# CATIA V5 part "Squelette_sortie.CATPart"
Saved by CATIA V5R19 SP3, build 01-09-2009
Part number: Squelette_sortie
Bounding box of the stored display mesh (mm): x 0 to 0, y 0 to 43, z -18 to 18
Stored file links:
  C:\Users\Frédéric\Documents\WF\STSCPI 09-11\Projets\Projet multiplicateur eolienne\Maquette eolienne\Squelette_sortie.CATPart
  C:\Users\Frédéric\Documents\WF\STSCPI 09-11\Projets\Projet multiplicateur eolienne\Maquette eolienne\Multiplicateur_eolien.CATProduct
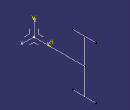
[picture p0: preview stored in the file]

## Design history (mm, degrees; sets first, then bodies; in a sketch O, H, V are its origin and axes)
External parameters (linked from other documents)
  `External.rayon primitif B et D` = 18 mm
AxisSystem1: origin (0, 0, 0), X (1, 0, 0), Y (0, 1, 0), Z (0, 0, 1)
Body1 (main body)
  Sketch1 on YZ plane of AxisSystem1, origin (0, 0, 0), H (0, 1, 0), V (0, 0, 1)
    line L1 (0, 0) -> (35, 0)
    point P1 (35, 0)
    line L2 (35, 0) -> (35, 18)
    point P2 (35, 18)
    line L3 (35, 18) -> (27, 18)
    point P3 (27, 18)
    line L4 (35, 18) -> (43, 18)
    point P4 (43, 18)
    point P5 (35, 0)
    point P6 (35, -18)
    point P7 (27, -18)
    point P8 (43, -18)
    line L5 (35, 0) -> (35, -18)
    line L6 (35, -18) -> (27, -18)
    line L7 (35, -18) -> (43, -18)
    length L1 = 35
    length L3 = 8 {= Sketch1.length(L4)}
    length L4 = 8
    length L2 = 18 {= `External.rayon primitif B et D`}
    horizontal: L1 H, L3 H, L4 H
    vertical: L2 V
    symmetry: P1 P5 L1, P2 P6 L1, P3 P7 L1, P4 P8 L1, L2 L5 L1, L3 L6 L1, L4 L7 L1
